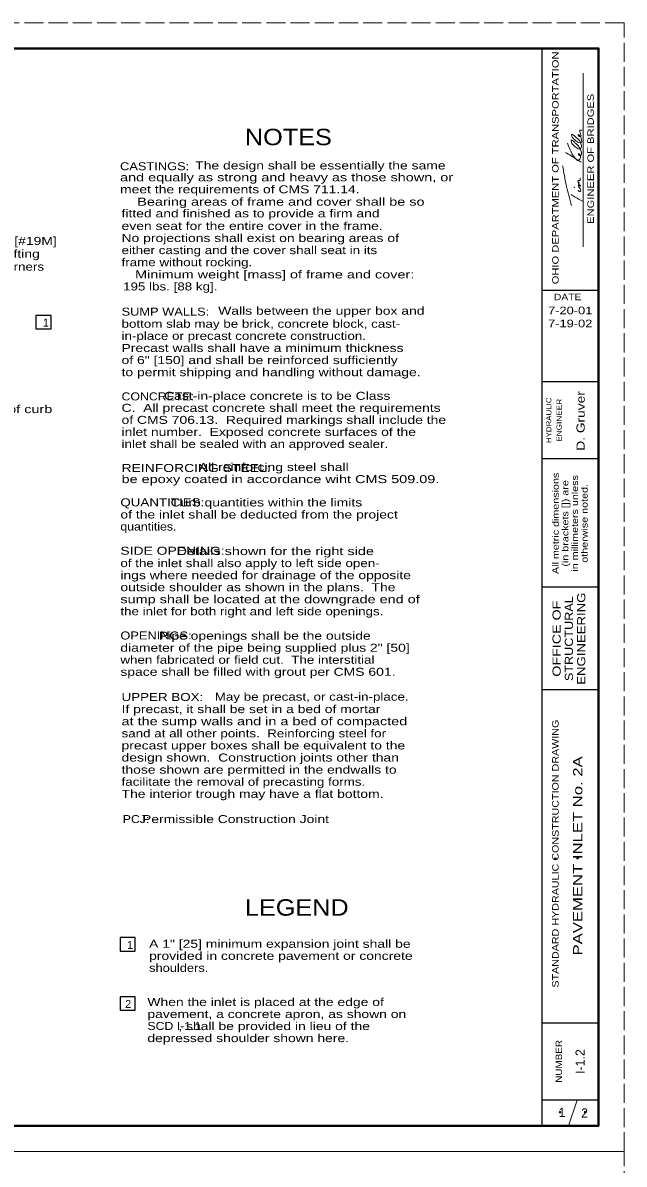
# Model space of a CAD drawing. Extents: x 758.3 to 792.3, y 849.7 to 893.7.
# Drawn here: x 780.59 to 792.32, y 871.44 to 893.69 of the extents above; entities that cross this region are included whole.
import ezdxf
from ezdxf.enums import TextEntityAlignment as Align

# ---------------------------------------------------------------- set-up
doc = ezdxf.new("R2010")
doc.units = 0
doc.header["$LTSCALE"] = 0.062
doc.header["$PDMODE"] = 32
doc.header["$PDSIZE"] = 0.031
doc.linetypes.add('LONG_DASHED', pattern=[7.5, 6, -1.5])
doc.layers.add('1', color=7, linetype='Continuous', lineweight=13)

msp = doc.modelspace()

# ---------------------------------------------------------------- linework, layer by layer
at = {"layer": '1', "lineweight": 25}
for p, q in [((760.3205, 893.18817), (791.8205, 893.18817)), ((790.7205, 872.18817), (790.7205, 893.18817)), ((791.8205, 893.18817), (791.8205, 872.18817)), ((791.8205, 888.47233), (790.7205, 888.47233)), ((791.8205, 886.68817), (790.7205, 886.68817)), ((791.8205, 885.18817), (790.7205, 885.18817)), ((791.8205, 882.68817), (790.7205, 882.68817)), ((791.8205, 880.68817), (790.7205, 880.68817)), ((791.8205, 874.18817), (790.7205, 874.18817)), ((791.8205, 872.68817), (790.7205, 872.68817))]:
    msp.add_line(p, q, dxfattribs=at)
at = {"layer": '1'}
for p, q in [((791.51925, 889.31917), (791.51925, 892.70925)), ((791.35175, 890.47008), (791.34158, 890.48933)), ((791.23717, 872.18817), (791.40383, 872.68817))]:
    msp.add_line(p, q, dxfattribs=at)
at = {"layer": '1', "linetype": 'LONG_DASHED'}
for points in [[(758.3205, 871.68817), (792.3205, 871.68817), (792.3205, 893.68817), (758.3205, 893.68817)], [(758.3205, 849.68817), (792.3205, 849.68817), (792.3205, 871.68817), (758.3205, 871.68817)]]:
    msp.add_lwpolyline(points, close=True, dxfattribs=at)
at = {"layer": '1', "lineweight": 25}
msp.add_lwpolyline([(791.8205, 872.18817), (760.3205, 872.18817), (760.3205, 893.18817)], dxfattribs=at)
at = {"layer": '1', "lineweight": 40}
msp.add_lwpolyline([(760.3205, 893.18817), (791.8205, 893.18817), (791.8205, 872.18817), (760.3205, 872.18817)], close=True, dxfattribs=at)
at = {"layer": '1', "lineweight": 25}
for points in [[(780.84325, 887.985), (780.84325, 887.72342), (781.14183, 887.72342), (781.14183, 887.985)], [(782.48442, 875.85417), (782.48442, 875.59258), (782.78308, 875.59258), (782.78308, 875.85417)], [(782.48442, 874.70142), (782.48442, 874.43967), (782.78308, 874.43967), (782.78308, 874.70142)]]:
    msp.add_lwpolyline(points, close=True, dxfattribs=at)
at = {"layer": '1'}
for points in [[(791.21233, 891.34517), (791.3955, 891.01683), (791.41067, 891.00625), (791.42083, 891.00625), (791.45275, 891.02992), (791.46783, 891.06408), (791.46283, 891.11533), (791.44592, 891.13717), (791.43242, 891.13717), (791.43067, 891.12417), (791.44083, 891.109), (791.45433, 891.10058), (791.46942, 891.10058), (791.48458, 891.12217), (791.488, 891.1415), (791.47775, 891.19683), (791.3955, 891.31725), (791.35, 891.36192), (791.31308, 891.3965), (791.28792, 891.39867), (791.28967, 891.36008), (791.31483, 891.32133), (791.38208, 891.259), (791.42417, 891.23358), (791.45783, 891.22908), (791.48117, 891.25508), (791.488, 891.28925), (791.48292, 891.315), (791.45275, 891.38817), (791.4225, 891.42017), (791.36192, 891.47358), (791.33325, 891.49942), (791.29975, 891.51467), (791.29633, 891.48667), (791.30642, 891.46083), (791.36358, 891.40092), (791.43425, 891.35367), (791.48625, 891.356), (791.48458, 891.41367), (791.47275, 891.45658), (791.45942, 891.48233), (791.44925, 891.49308), (791.42583, 891.50808), (791.42758, 891.491), (791.46283, 891.4695), (791.47775, 891.48025), (791.46467, 891.53392), (791.45608, 891.56183), (791.45275, 891.5745), (791.45275, 891.58733), (791.45275, 891.596), (791.47775, 891.59383), (791.50317, 891.59383)], [(791.1735, 891.16292), (791.39725, 891.02542), (791.48292, 890.96975)], [(791.28975, 890.12592), (791.19108, 890.52117), (791.11983, 890.9035)], [(791.42083, 890.42483), (791.42908, 890.41417), (791.46625, 890.40125), (791.471, 890.43367), (791.44592, 890.47008), (791.43067, 890.50633), (791.43067, 890.52558), (791.44592, 890.51933), (791.45608, 890.5085), (791.46625, 890.50417), (791.44258, 890.53633), (791.43067, 890.55133), (791.42758, 890.56867), (791.451, 890.56208), (791.44258, 890.57075), (791.41742, 890.59858), (791.42758, 890.61375), (791.44433, 890.61575), (791.45275, 890.61375), (791.46283, 890.63508), (791.45608, 890.663)], [(791.50492, 890.21033), (791.29975, 890.33033), (791.28417, 890.34075)]]:
    msp.add_spline(points, degree=3, dxfattribs=at)
for p in [(790.97792, 877.39417), (791.41075, 877.4015), (791.06858, 872.45192), (791.557, 872.45092)]:
    msp.add_point(p, dxfattribs=at)

# ---------------------------------------------------------------- texts
for s, height, width, p in [('OHIO DEPARTMENT OF TRANSPORTATION', 0.125, 1.3, (791.04042, 890.86042)), ('ENGINEER OF BRIDGES', 0.125, 1.3, (791.72875, 891.03721)), ('D. Gruver', 0.16, 1.25, (791.5505, 885.92742)), ('HYDRAULIC', 0.1, 1.15, (790.89958, 885.93925)), ('ENGINEER', 0.1, 1.2, (791.1005, 885.93929)), ('All metric dimensions', 0.125, 1.25, (791.04433, 883.93025)), ('(in brackets []) are', 0.125, 1.25, (791.23183, 883.93025)), ('in millimeters unless', 0.125, 1.25, (791.41933, 883.93029)), ('otherwise noted.', 0.125, 1.25, (791.60683, 883.93025)), ('STRUCTURAL', 0.16, 1.15, (791.32225, 881.68262)), ('ENGINEERING', 0.16, 1.2, (791.56225, 881.68271)), ('OFFICE OF', 0.16, 1.3, (791.08225, 881.68262)), ('STANDARD HYDRAULIC CONSTRUCTION DRAWING', 0.125, 1.25, (791.04042, 877.49221)), ('PAVEMENT INLET No. 2A', 0.18, 1.35, (791.50425, 877.44833)), ('NUMBER', 0.125, 1.15, (791.1075, 873.44225))]:
    msp.add_text(s, height=height, rotation=90, dxfattribs=dict(at, width=width)).set_placement(p, align=Align.CENTER)
for s, height, width, p in [('NOTES', 0.32, 1.15, (784.9215, 891.30242)), ('CASTINGS:', 0.156, 1.2, (782.4855, 890.814)), (' The design shall be essentially the same ', 0.156, 1.3, (783.8765, 890.82983)), ('and equally as strong and heavy as those shown, or ', 0.156, 1.35, (782.48542, 890.59883)), ('meet the requirements of CMS 711.14.', 0.156, 1.3, (782.48542, 890.36483)), ('Bearing areas of frame and cover shall be so', 0.156, 1.35, (782.82092, 890.12308)), ('fitted and finished as to provide a firm and', 0.156, 1.3, (782.514, 889.89575)), ('even seat for the entire cover in the frame.', 0.156, 1.3, (782.51475, 889.65108)), ('No projections shall exist on bearing areas of', 0.156, 1.3, (782.51475, 889.41508)), ('Lift holes or #6 [#19M]', 0.156, 1.3, (778.56775, 889.35875)), ('either casting and the cover shall seat in its', 0.156, 1.25, (782.51475, 889.17908)), ('bar used as a lifting', 0.156, 1.3, (778.56775, 889.10758)), ('lug at all four corners', 0.156, 1.25, (778.56775, 888.85642)), ('frame without rocking.', 0.156, 1.25, (782.51475, 888.94308)), ('   Minimum weight [mass] of frame and cover:', 0.156, 1.35, (782.54442, 888.70575)), ('195 lbs. [88 kg].', 0.156, 1.25, (782.54442, 888.47108)), ('SUMP WALLS:', 0.156, 1.2, (782.51475, 887.97967)), ('Walls between the upper box and', 0.156, 1.3, (784.39975, 887.99717)), ('bottom slab may be brick, concrete block, cast-', 0.156, 1.25, (782.51475, 887.74367)), ('in-place or precast concrete construction.', 0.156, 1.25, (782.51475, 887.50767)), ('Precast walls shall have a minimum thickness', 0.156, 1.3, (782.51475, 887.27167)), ('of 6" [150] and shall be reinforced sufficiently', 0.156, 1.3, (782.51475, 887.03567)), ('to permit shipping and handling without damage.', 0.156, 1.3, (782.51475, 886.79967)), ('CONCRETE:', 0.156, 1.15, (782.51475, 886.32767)), ('           Cast-in-place concrete is to be Class ', 0.156, 1.3, (782.51475, 886.339)), ('Face of curb', 0.156, 1.35, (779.59892, 886.07983)), ('C.  All precast concrete shall meet the requirements ', 0.156, 1.3, (782.51475, 886.10433)), ('of CMS 706.13.  Required markings shall include the ', 0.156, 1.3, (782.51475, 885.86967)), ('inlet number.  Exposed concrete surfaces of the', 0.156, 1.3, (782.51475, 885.635)), ('inlet shall be sealed with an approved sealer.', 0.156, 1.25, (782.51475, 885.40033)), ('                    All reinforcing steel shall', 0.156, 1.3, (782.51475, 884.94983)), ('REINFORCING STEEL:', 0.156, 1.3, (782.51475, 884.93175)), ('be epoxy coated in accordance wiht CMS 509.09.', 0.156, 1.35, (782.51475, 884.71517)), ('QUANTITIES:', 0.156, 1.25, (782.49158, 884.26258)), ('             Curb quantities within the limits', 0.156, 1.3, (782.4915, 884.25992)), ('of the inlet shall be deducted from the project', 0.156, 1.3, (782.4915, 884.02525)), ('quantities.', 0.156, 1.15, (782.4915, 883.79058)), ('SIDE OPENING:', 0.156, 1.3, (782.49158, 883.31858)), ('              Details shown for the right side', 0.156, 1.35, (782.4915, 883.31192)), ('of the inlet shall also apply to left side open-', 0.156, 1.25, (782.4915, 883.07725)), ('ings where needed for drainage of the opposite', 0.156, 1.3, (782.4915, 882.84258)), ('outside shoulder as shown in the plans.  The', 0.156, 1.3, (782.4915, 882.60792)), ('sump shall be located at the downgrade end of', 0.156, 1.35, (782.4915, 882.37325)), ('the inlet for both right and left side openings.', 0.156, 1.25, (782.4915, 882.13858)), ('OPENINGS:', 0.156, 1.2, (782.49158, 881.66658)), ('          Pipe openings shall be the outside', 0.156, 1.3, (782.4915, 881.66258)), ('diameter of the pipe being supplied plus 2" [50]', 0.156, 1.3, (782.4915, 881.42792)), ('when fabricated or field cut.  The interstitial', 0.156, 1.25, (782.4915, 881.19325)), ('space shall be filled with grout per CMS 601.', 0.156, 1.3, (782.4915, 880.95858)), ('UPPER BOX:', 0.156, 1.25, (782.51475, 880.46717)), ('May be precast, or cast-in-place.', 0.156, 1.25, (784.33317, 880.47342)), ('If precast, it shall be set in a bed of mortar', 0.156, 1.3, (782.51475, 880.23117)), ('at the sump walls and in a bed of compacted', 0.156, 1.35, (782.51475, 879.99517)), ('sand at all other points.  Reinforcing steel for', 0.156, 1.25, (782.51475, 879.75917)), ('precast upper boxes shall be equivalent to the', 0.156, 1.3, (782.51475, 879.52317)), ('design shown.  Construction joints other than', 0.156, 1.3, (782.51475, 879.28717)), ('those shown are permitted in the endwalls to', 0.156, 1.3, (782.51475, 879.05117)), ('facilitate the removal of precasting forms.', 0.156, 1.25, (782.51475, 878.81517)), ('The interior trough may have a flat bottom.', 0.156, 1.3, (782.51475, 878.57917)), ('PCJ:', 0.156, 1.15, (782.538, 878.08775)), ('     Permissible Construction Joint', 0.156, 1.3, (782.538, 878.08775)), ('LEGEND', 0.32, 1.15, (784.9215, 876.28275)), ('A 1" [25] minimum expansion joint shall be', 0.156, 1.3, (783.05242, 875.65608)), ('provided in concrete pavement or concrete', 0.156, 1.3, (783.05242, 875.42142)), ('shoulders.', 0.156, 1.2, (783.05242, 875.18675)), ('When the inlet is placed at the edge of', 0.156, 1.3, (783.0185, 874.5215)), ('pavement, a concrete apron, as shown on', 0.156, 1.3, (783.0185, 874.28683)), ('SCD I-1.1', 0.156, 1.15, (783.01867, 874.05483)), ('        , shall be provided in lieu of the', 0.156, 1.3, (783.0185, 874.05217)), ('depressed shoulder shown here.', 0.156, 1.3, (783.0185, 873.8175))]:
    msp.add_text(s, height=height, dxfattribs=dict(at, width=width)).set_placement(p)
for s, height, width, p in [('DATE', 0.125, 1.2, (791.21721, 888.28092)), ('7-20-01', 0.15, 1.25, (791.26754, 888.00542)), ('7-19-02', 0.15, 1.25, (791.26754, 887.75233))]:
    msp.add_text(s, height=height, dxfattribs=dict(at, width=width)).set_placement(p, align=Align.CENTER)
for s, p in [('1', (780.982, 887.76592)), ('1', (782.62325, 875.63508)), ('2', (782.58633, 874.48325))]:
    msp.add_text(s, height=0.156, dxfattribs=at).set_placement(p)
msp.add_text('I-1.2', height=0.18, rotation=90, dxfattribs=at).set_placement((791.55117, 873.4385), align=Align.CENTER)
for s, p in [('1', (791.10835, 872.35825)), ('2', (791.54779, 872.34567))]:
    msp.add_text(s, height=0.18, dxfattribs=at).set_placement(p, align=Align.CENTER)

doc.saveas('drawing.dxf')
